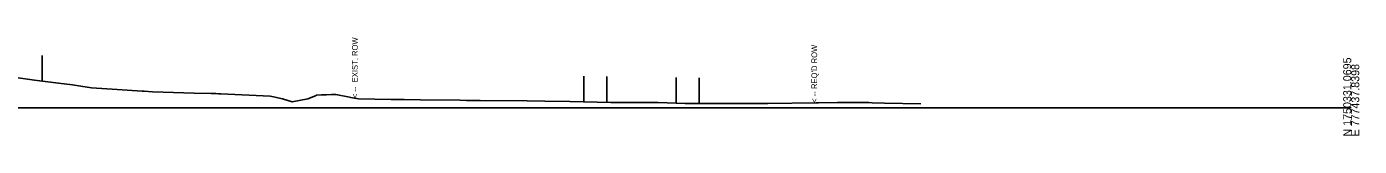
# Model space of a CAD drawing. Extents: x 776426 to 854588, y 1736205 to 1756790.
# Drawn here: x 805207.3 to 805673.6, y 1749705.1 to 1749739.5 of the extents above; entities that cross this region are included whole.
import ezdxf

# ---------------------------------------------------------------- set-up
doc = ezdxf.new("R2010")
doc.units = 0
for name, color, linetype in [('63', 7, 'Continuous'), ('DTM CONTOURS_MAJOR_TX', 7, 'Continuous'), ('DTM_X_FLOW_ARROWS', 7, 'Continuous'), ('TRANS_EOP_PAVED', 7, 'Continuous'), ('TRANS_UNPAVED_SHOULDERS', 7, 'Continuous'), ('XS_P_ROW', 7, 'Continuous'), ('XS_X_ROW', 7, 'Continuous')]:
    doc.layers.add(name, color=color, linetype=linetype)

msp = doc.modelspace()

# ---------------------------------------------------------------- linework, layer by layer
at = {"layer": '63'}
msp.add_line((805212.79, 1749733.17), (805212.79, 1749724.17), dxfattribs=at)
msp.add_line((805212.79, 1749733.17), (805212.79, 1749724.17), dxfattribs=at)
at = {"layer": 'DTM CONTOURS_MAJOR_TX'}
msp.add_line((805170.79, 1749714.76), (805670.79, 1749714.76), dxfattribs=at)
at = {"layer": 'DTM_X_FLOW_ARROWS'}
msp.add_lwpolyline([(805203.57, 1749725.42), (805209.19, 1749724.62), (805210.07, 1749724.52), (805211.97, 1749724.27), (805216.56, 1749723.72), (805218.5, 1749723.46), (805223.32, 1749722.84), (805226.29, 1749722.36), (805230.04, 1749721.84), (805238.97, 1749721.25), (805247.76, 1749720.69), (805248.48, 1749720.63), (805251.37, 1749720.47), (805255.02, 1749720.25), (805265.9, 1749719.97), (805271.87, 1749719.83), (805272.39, 1749719.82), (805272.72, 1749719.81), (805273.54, 1749719.78), (805274.46, 1749719.76), (805275.26, 1749719.71), (805292.49, 1749718.94), (805294.31, 1749718.53), (805295.25, 1749718.32), (805296.87, 1749717.97), (805300.18, 1749716.95), (805305.71, 1749717.95), (805308.34, 1749719.05), (805308.78, 1749719.23), (805310.53, 1749719.35), (805312.26, 1749719.41), (805314.01, 1749719.5), (805315.43, 1749719.5), (805316.08, 1749719.37), (805319.72, 1749718.61), (805321.3, 1749718.31), (805323.39, 1749717.99), (805334.84, 1749717.74), (805339.37, 1749717.71), (805345.1, 1749717.65), (805358.98, 1749717.45), (805361.22, 1749717.43), (805362.45, 1749717.42), (805366.02, 1749717.43), (805382.45, 1749717.22), (805388.68, 1749717.17), (805397.43, 1749717.07), (805411.7, 1749716.71), (805418.43, 1749716.7), (805424.34, 1749716.63), (805428.23, 1749716.69), (805437.78, 1749716.38), (805438.43, 1749716.37), (805442.44, 1749716.36), (805447.24, 1749716.31), (805464.01, 1749716.34), (805466.39, 1749716.34), (805466.7, 1749716.34), (805483.51, 1749716.57), (805484.4, 1749716.58), (805491.04, 1749716.7), (805502.02, 1749716.64), (805503.22, 1749716.58), (805507.51, 1749716.44), (805520.23, 1749716.17)], dxfattribs=at)
at = {"layer": 'TRANS_EOP_PAVED'}
for p, q in [((805410.34, 1749725.74), (805410.34, 1749716.74)), ((805410.34, 1749725.74), (805410.34, 1749716.74)), ((805434.53, 1749725.49), (805434.53, 1749716.49)), ((805434.53, 1749725.49), (805434.53, 1749716.49))]:
    msp.add_line(p, q, dxfattribs=at)
at = {"layer": 'TRANS_UNPAVED_SHOULDERS'}
for p, q in [((805402.28, 1749725.95), (805402.28, 1749716.95)), ((805402.28, 1749725.95), (805402.28, 1749716.95)), ((805442.6, 1749725.36), (805442.6, 1749716.36)), ((805442.6, 1749725.36), (805442.6, 1749716.36))]:
    msp.add_line(p, q, dxfattribs=at)

# ---------------------------------------------------------------- texts
at = {"layer": 'DTM CONTOURS_MAJOR_TX'}
for s, p in [('N 1750331.0695', (805670.79, 1749704.76)), ('E 777437.8398', (805673.59, 1749704.76))]:
    msp.add_text(s, height=2.8, rotation=90, dxfattribs=at).set_placement(p)
at = {"layer": 'XS_P_ROW'}
msp.add_text("< -- REQ'D ROW", height=2, rotation=90, dxfattribs=at).set_placement((805483.91, 1749716.56))
at = {"layer": 'XS_X_ROW'}
msp.add_text('< --  EXIST. ROW', height=2, rotation=90, dxfattribs=at).set_placement((805323.16, 1749718.18))

doc.saveas('drawing.dxf')
